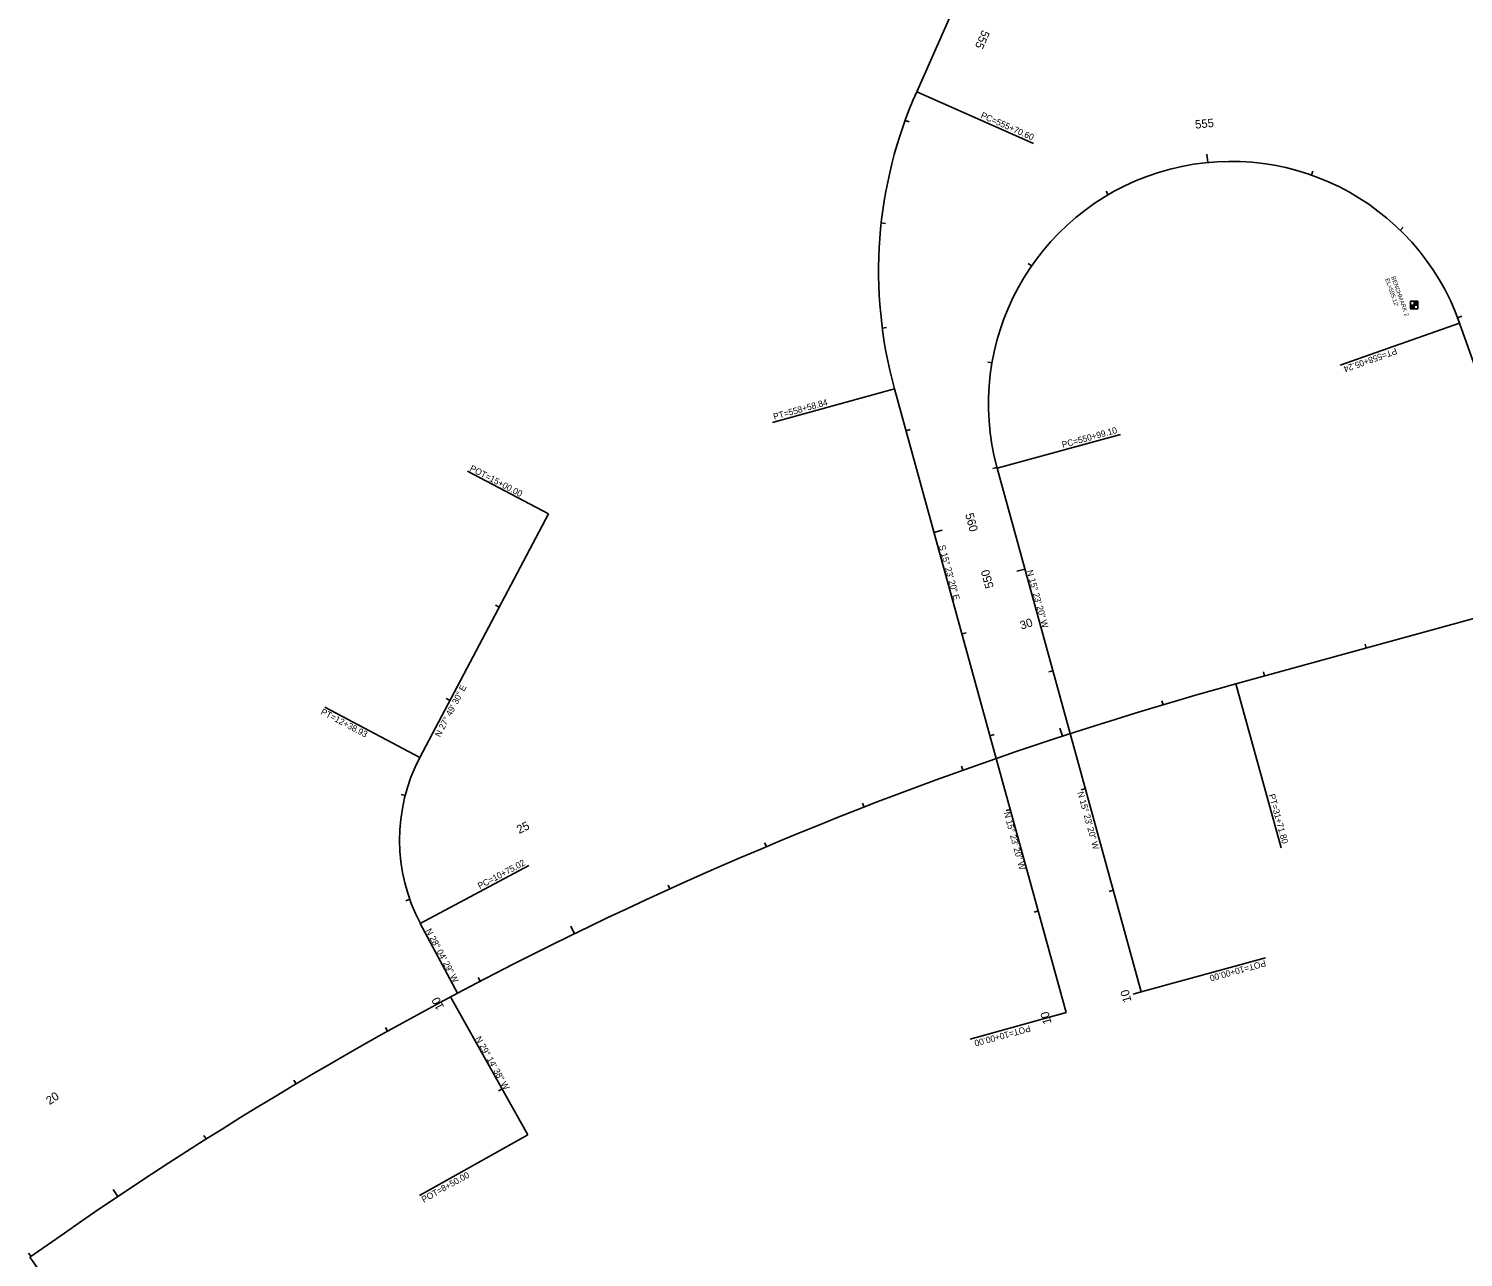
# Model space of a CAD drawing. Extents: x 2004390 to 2008791, y 1133870 to 1140084.
# Drawn here: x 2004390 to 2005751, y 1136432 to 1137597 of the extents above; entities that cross this region are included whole.
import ezdxf

# ---------------------------------------------------------------- set-up
doc = ezdxf.new("R2010")
doc.units = 0
for name, color, linetype in [('RD_HC_Cl', 7, 'Continuous'), ('RD_HC_CL_Rel', 7, 'Continuous'), ('RD_HC_Data', 7, 'Continuous'), ('RD_HC_Data_Rel', 7, 'Continuous'), ('RD_HC_Data_Tic', 7, 'Continuous'), ('RD_HC_Data_Tic_Rel', 7, 'Continuous'), ('RD_HC_Survey', 7, 'Continuous'), ('RD_HC_Survey_txCode', 7, 'Continuous'), ('RD_HC_TX_Rel_Sta50', 7, 'Continuous'), ('RD_HC_TX_Sta50', 7, 'Continuous')]:
    doc.layers.add(name, color=color, linetype=linetype)

msp = doc.modelspace()

# ---------------------------------------------------------------- linework, layer by layer
at = {"layer": 'RD_HC_Cl'}
for p, q in [((2005379.4, 1137869.6), (2005232, 1137537.6)), ((2005747, 1137318.2), (2006250.3, 1135895.5)), ((2005211, 1137255.8), (2005307.4, 1136905.2)), ((2005377.7, 1136928.8), (2005308.4, 1137180.5)), ((2004760.8, 1136906.3), (2004882.7, 1137137.2)), ((2005445.1, 1136683.8), (2005377.7, 1136928.8)), ((2005373.8, 1136664.2), (2005307.4, 1136905.2)), ((2004796.5, 1136682.6), (2004761.1, 1136748.8)), ((2004863.1, 1136548.2), (2004789.8, 1136679.1))]:
    msp.add_line(p, q, dxfattribs=at)
for centre, radius, start, end in [((2005615.9, 1137367.2), 420, 156.0681, 195.3889), ((2005530.2, 1137241.5), 230, 19.482, 195.3889), ((2004909.4, 1136827.9), 168, 152.175, 208.0747)]:
    msp.add_arc(centre, radius, start, end, dxfattribs=at)
at = {"layer": 'RD_HC_CL_Rel'}
msp.add_line((2005534.9, 1136975.9), (2006420.4, 1137219.7), dxfattribs=at)
msp.add_arc((2006499.8, 1133470.3), 3636, 105.3889, 125.452, dxfattribs=at)
at = {"layer": 'RD_HC_Data'}
for p, q in [((2005232, 1137537.6), (2005342.7, 1137488.5)), ((2005747, 1137318.2), (2005633.8, 1137278.2)), ((2005095.2, 1137223.9), (2005211, 1137255.8)), ((2005308.4, 1137180.5), (2005425.2, 1137212.6)), ((2004882.7, 1137137.2), (2004805.8, 1137177.8)), ((2004670.5, 1136954), (2004760.8, 1136906.3)), ((2004761.1, 1136748.8), (2004864, 1136803.7)), ((2005562.8, 1136716.2), (2005445.1, 1136683.8)), ((2005373.8, 1136664.2), (2005282.8, 1136639.1)), ((2004863.1, 1136548.2), (2004760.5, 1136490.8))]:
    msp.add_line(p, q, dxfattribs=at)
at = {"layer": 'RD_HC_Data_Rel'}
for p, q in [((2005534.9, 1136975.9), (2005577.7, 1136820.4)), ((2004390.8, 1136432.2), (2004485.4, 1136299.3))]:
    msp.add_line(p, q, dxfattribs=at)
at = {"layer": 'RD_HC_Data_Tic'}
for p, q in [((2005221, 1137510.3), (2005224.8, 1137509)), ((2005508.1, 1137470.5), (2005507.3, 1137478.4)), ((2005606.6, 1137458.5), (2005607.9, 1137462.2)), ((2005413.7, 1137439.8), (2005411.7, 1137443.3)), ((2005198.4, 1137413.2), (2005202.4, 1137412.7)), ((2005690.8, 1137406.1), (2005693.6, 1137409)), ((2005341, 1137372.3), (2005337.7, 1137374.6)), ((2005199.4, 1137313.4), (2005203.3, 1137313.9)), ((2005745.2, 1137323.1), (2005749, 1137324.6)), ((2005303.5, 1137280.4), (2005299.6, 1137281.1)), ((2005221.9, 1137216.1), (2005225.7, 1137217.1)), ((2005308.2, 1137181.3), (2005304.3, 1137180.3)), ((2005248.4, 1137119.7), (2005256.1, 1137121.8)), ((2005334.7, 1137084.9), (2005327, 1137082.8)), ((2004836, 1137048.8), (2004832.5, 1137050.6)), ((2005275, 1137023.3), (2005278.8, 1137024.3)), ((2005361.3, 1136988.5), (2005357.4, 1136987.5)), ((2004789.3, 1136960.3), (2004785.8, 1136962.2)), ((2005301.5, 1136926.8), (2005305.4, 1136927.9)), ((2005392.1, 1136876.7), (2005388.2, 1136875.6)), ((2004746.8, 1136870.1), (2004742.9, 1136871.1)), ((2005320.7, 1136857), (2005316.9, 1136856)), ((2004751.1, 1136771.7), (2004747.3, 1136770.3)), ((2005418.6, 1136780.2), (2005414.7, 1136779.2)), ((2005347.3, 1136760.6), (2005343.4, 1136759.5)), ((2004796.5, 1136682.6), (2004789.4, 1136678.9)), ((2005445.1, 1136683.8), (2005437.4, 1136681.7)), ((2005373.8, 1136664.2), (2005366.1, 1136662.1)), ((2004838.7, 1136591.9), (2004835.2, 1136589.9))]:
    msp.add_line(p, q, dxfattribs=at)
at = {"layer": 'RD_HC_Data_Tic_Rel'}
for p, q in [((2005658.5, 1137009.9), (2005657.4, 1137013.8)), ((2005562.1, 1136983.4), (2005561, 1136987.3)), ((2005465.8, 1136956.2), (2005464.7, 1136960)), ((2005370.4, 1136926.4), (2005367.9, 1136934)), ((2005275.8, 1136894.1), (2005274.4, 1136897.8)), ((2005182.1, 1136859.1), (2005180.6, 1136862.8)), ((2005089.4, 1136821.6), (2005087.8, 1136825.3)), ((2004997.8, 1136781.5), (2004996.1, 1136785.2)), ((2004907.3, 1136739), (2004903.8, 1136746.2)), ((2004818, 1136694), (2004816.1, 1136697.5)), ((2004730, 1136646.5), (2004728, 1136650)), ((2004643.3, 1136596.6), (2004641.2, 1136600.1)), ((2004558, 1136544.4), (2004555.9, 1136547.8)), ((2004474.2, 1136489.8), (2004469.8, 1136496.5)), ((2004391.9, 1136433), (2004389.6, 1136436.2))]:
    msp.add_line(p, q, dxfattribs=at)
at = {"layer": 'RD_HC_Survey'}
for p, q in [((2005704, 1137338.8), (2005704, 1137331.7)), ((2005704, 1137338.8), (2005704, 1137335.2)), ((2005704.1, 1137338.8), (2005704.1, 1137335.2)), ((2005704.1, 1137338.8), (2005704.1, 1137335.2)), ((2005704.2, 1137338.8), (2005704.2, 1137335.2)), ((2005704.2, 1137338.8), (2005704.2, 1137335.2)), ((2005704.3, 1137338.8), (2005704.3, 1137335.2)), ((2005704.3, 1137338.8), (2005704.3, 1137335.2)), ((2005704.4, 1137338.8), (2005704.4, 1137335.2)), ((2005704.4, 1137338.8), (2005704.4, 1137335.2)), ((2005704.5, 1137338.8), (2005704.5, 1137335.2)), ((2005704.5, 1137338.8), (2005704.5, 1137335.2)), ((2005704.6, 1137338.8), (2005704.6, 1137335.2)), ((2005704.6, 1137338.8), (2005704.6, 1137335.2)), ((2005704.7, 1137338.8), (2005704.7, 1137335.2)), ((2005704.7, 1137338.8), (2005704.7, 1137335.2)), ((2005704.8, 1137338.8), (2005704.8, 1137335.2)), ((2005704.8, 1137338.8), (2005704.8, 1137335.2)), ((2005704.9, 1137338.8), (2005704.9, 1137335.2)), ((2005704.9, 1137338.8), (2005704.9, 1137335.2)), ((2005705, 1137338.8), (2005705, 1137335.2)), ((2005705, 1137338.8), (2005705, 1137335.2)), ((2005705.1, 1137338.8), (2005705.1, 1137335.2)), ((2005705.1, 1137338.8), (2005705.1, 1137335.2)), ((2005705.2, 1137338.8), (2005705.2, 1137335.2)), ((2005705.2, 1137338.8), (2005705.2, 1137335.2)), ((2005705.3, 1137338.8), (2005705.3, 1137335.2)), ((2005705.3, 1137338.8), (2005705.3, 1137335.2)), ((2005705.4, 1137338.8), (2005705.4, 1137335.2)), ((2005705.4, 1137338.8), (2005705.4, 1137335.2)), ((2005705.5, 1137338.8), (2005705.5, 1137335.2)), ((2005705.5, 1137338.8), (2005705.5, 1137335.2)), ((2005705.6, 1137338.8), (2005705.6, 1137335.2)), ((2005705.6, 1137338.8), (2005705.6, 1137335.2)), ((2005705.7, 1137338.8), (2005705.7, 1137335.2)), ((2005705.7, 1137338.8), (2005705.7, 1137335.2)), ((2005705.8, 1137338.8), (2005705.8, 1137335.2)), ((2005705.8, 1137338.8), (2005705.8, 1137335.2)), ((2005705.9, 1137338.8), (2005705.9, 1137335.2)), ((2005705.9, 1137338.8), (2005705.9, 1137335.2)), ((2005706, 1137338.8), (2005706, 1137335.2)), ((2005706, 1137338.8), (2005706, 1137335.2)), ((2005706.1, 1137338.8), (2005706.1, 1137335.2)), ((2005706.1, 1137338.8), (2005706.1, 1137335.2)), ((2005706.2, 1137338.8), (2005706.2, 1137335.2)), ((2005706.2, 1137338.8), (2005706.2, 1137335.2)), ((2005706.3, 1137338.8), (2005706.3, 1137335.2)), ((2005706.3, 1137338.8), (2005706.3, 1137335.2)), ((2005706.4, 1137338.8), (2005706.4, 1137335.2)), ((2005706.4, 1137338.8), (2005706.4, 1137335.2)), ((2005706.5, 1137338.8), (2005706.5, 1137335.2)), ((2005706.5, 1137338.8), (2005706.5, 1137335.2)), ((2005706.6, 1137338.8), (2005706.6, 1137335.2)), ((2005706.6, 1137338.8), (2005706.6, 1137335.2)), ((2005706.7, 1137338.8), (2005706.7, 1137335.2)), ((2005706.7, 1137338.8), (2005706.7, 1137335.2)), ((2005706.8, 1137338.8), (2005706.8, 1137335.2)), ((2005706.8, 1137338.8), (2005706.8, 1137335.2)), ((2005706.9, 1137338.8), (2005706.9, 1137335.2)), ((2005706.9, 1137338.8), (2005706.9, 1137335.2)), ((2005707, 1137338.8), (2005707, 1137335.2)), ((2005707, 1137338.8), (2005707, 1137335.2)), ((2005707.1, 1137338.8), (2005707.1, 1137335.2)), ((2005707.1, 1137338.8), (2005707.1, 1137335.2)), ((2005707.2, 1137338.8), (2005707.2, 1137335.2)), ((2005707.2, 1137338.8), (2005707.2, 1137335.2)), ((2005707.3, 1137338.8), (2005707.3, 1137335.2)), ((2005707.3, 1137338.8), (2005707.3, 1137335.2)), ((2005707.4, 1137338.8), (2005707.4, 1137335.2)), ((2005707.4, 1137338.8), (2005707.4, 1137335.2)), ((2005707.5, 1137338.8), (2005707.5, 1137335.2)), ((2005707.5, 1137335.2), (2005700.4, 1137335.2)), ((2005700.4, 1137335.2), (2005700.4, 1137331.7)), ((2005700.5, 1137335.2), (2005700.5, 1137331.7)), ((2005700.5, 1137335.2), (2005700.5, 1137331.7)), ((2005700.6, 1137335.2), (2005700.6, 1137331.7)), ((2005700.6, 1137335.2), (2005700.6, 1137331.7)), ((2005700.7, 1137335.2), (2005700.7, 1137331.7)), ((2005700.7, 1137335.2), (2005700.7, 1137331.7)), ((2005700.8, 1137335.2), (2005700.8, 1137331.7)), ((2005700.8, 1137335.2), (2005700.8, 1137331.7)), ((2005700.9, 1137335.2), (2005700.9, 1137331.7)), ((2005700.9, 1137335.2), (2005700.9, 1137331.7)), ((2005701, 1137335.2), (2005701, 1137331.7)), ((2005701, 1137335.2), (2005701, 1137331.7)), ((2005701.1, 1137335.2), (2005701.1, 1137331.7)), ((2005701.1, 1137335.2), (2005701.1, 1137331.7)), ((2005701.2, 1137335.2), (2005701.2, 1137331.7)), ((2005701.2, 1137335.2), (2005701.2, 1137331.7)), ((2005701.3, 1137335.2), (2005701.3, 1137331.7)), ((2005701.3, 1137335.2), (2005701.3, 1137331.7)), ((2005701.4, 1137335.2), (2005701.4, 1137331.7)), ((2005701.4, 1137335.2), (2005701.4, 1137331.7)), ((2005701.5, 1137335.2), (2005701.5, 1137331.7)), ((2005701.5, 1137335.2), (2005701.5, 1137331.7)), ((2005701.6, 1137335.2), (2005701.6, 1137331.7)), ((2005701.6, 1137335.2), (2005701.6, 1137331.7)), ((2005701.7, 1137335.2), (2005701.7, 1137331.7)), ((2005701.7, 1137335.2), (2005701.7, 1137331.7)), ((2005701.8, 1137335.2), (2005701.8, 1137331.7)), ((2005701.8, 1137335.2), (2005701.8, 1137331.7)), ((2005701.9, 1137335.2), (2005701.9, 1137331.7)), ((2005701.9, 1137335.2), (2005701.9, 1137331.7)), ((2005702, 1137335.2), (2005702, 1137331.7)), ((2005702, 1137335.2), (2005702, 1137331.7)), ((2005702.1, 1137335.2), (2005702.1, 1137331.7)), ((2005702.1, 1137335.2), (2005702.1, 1137331.7)), ((2005702.2, 1137335.2), (2005702.2, 1137331.7)), ((2005702.2, 1137335.2), (2005702.2, 1137331.7)), ((2005702.3, 1137335.2), (2005702.3, 1137331.7)), ((2005702.3, 1137335.2), (2005702.3, 1137331.7)), ((2005702.4, 1137335.2), (2005702.4, 1137331.7)), ((2005702.4, 1137335.2), (2005702.4, 1137331.7)), ((2005702.5, 1137335.2), (2005702.5, 1137331.7)), ((2005702.5, 1137335.2), (2005702.5, 1137331.7)), ((2005702.6, 1137335.2), (2005702.6, 1137331.7)), ((2005702.6, 1137335.2), (2005702.6, 1137331.7)), ((2005702.7, 1137335.2), (2005702.7, 1137331.7)), ((2005702.7, 1137335.2), (2005702.7, 1137331.7)), ((2005702.8, 1137335.2), (2005702.8, 1137331.7)), ((2005702.8, 1137335.2), (2005702.8, 1137331.7)), ((2005702.9, 1137335.2), (2005702.9, 1137331.7)), ((2005702.9, 1137335.2), (2005702.9, 1137331.7)), ((2005703, 1137335.2), (2005703, 1137331.7)), ((2005703, 1137335.2), (2005703, 1137331.7)), ((2005703.1, 1137335.2), (2005703.1, 1137331.7)), ((2005703.1, 1137335.2), (2005703.1, 1137331.7)), ((2005703.2, 1137335.2), (2005703.2, 1137331.7)), ((2005703.2, 1137335.2), (2005703.2, 1137331.7)), ((2005703.3, 1137335.2), (2005703.3, 1137331.7)), ((2005703.3, 1137335.2), (2005703.3, 1137331.7)), ((2005703.4, 1137335.2), (2005703.4, 1137331.7)), ((2005703.4, 1137335.2), (2005703.4, 1137331.7)), ((2005703.5, 1137335.2), (2005703.5, 1137331.7)), ((2005703.5, 1137335.2), (2005703.5, 1137331.7)), ((2005703.6, 1137335.2), (2005703.6, 1137331.7)), ((2005703.6, 1137335.2), (2005703.6, 1137331.7)), ((2005703.7, 1137335.2), (2005703.7, 1137331.7)), ((2005703.7, 1137335.2), (2005703.7, 1137331.7)), ((2005703.8, 1137335.2), (2005703.8, 1137331.7)), ((2005703.8, 1137335.2), (2005703.8, 1137331.7)), ((2005703.9, 1137335.2), (2005703.9, 1137331.7)), ((2005703.9, 1137335.2), (2005703.9, 1137331.7))]:
    msp.add_line(p, q, dxfattribs=at)
msp.add_lwpolyline([(2005707.5, 1137338.8), (2005700.4, 1137338.8), (2005700.4, 1137331.7), (2005707.5, 1137331.7)], close=True, dxfattribs=at)

# ---------------------------------------------------------------- texts
at = {"layer": 'RD_HC_Data'}
for s, rotation, p in [('PC=555+70.60', 336.0681, (2005292.2, 1137513.1)), ('PT=558+05.24', 199.482, (2005686.4, 1137294.7)), ('PT=558+58.84', 15.3889, (2005096.9, 1137226.4)), ('PC=550+99.10', 15.3889, (2005370.6, 1137199.7)), ('POT=15+00.00', 332.175, (2004807.5, 1137178.6)), ('S 15%%d 23\' 20" E', 285.3889, (2005253, 1137106.9)), ('N 15%%d 23\' 20" W', 285.3889, (2005336.3, 1137083.1)), ('N 27%%d 49\' 30" E', 62.175, (2004779.8, 1136925)), ('PT=12+38.93', 332.175, (2004666.1, 1136947.6)), ('N 15%%d 23\' 20" W', 285.3889, (2005384.5, 1136873)), ('N 15%%d 23\' 20" W', 285.3889, (2005314.5, 1136853.8)), ('PC=10+75.02', 28.0747, (2004817.6, 1136781.2)), ('N 28%%d 04\' 29" W', 298.0747, (2004765.9, 1136742)), ('POT=10+00.00', 195.3889, (2005562.3, 1136714.1)), ('POT=10+00.00', 195.3889, (2005339.1, 1136652.3)), ('N 29%%d 14\' 38" W', 299.2438, (2004813.1, 1136639.7)), ('POT=8+50.00', 29.2438, (2004764.4, 1136483.8))]:
    msp.add_text(s, height=6, rotation=rotation, dxfattribs=at).set_placement(p)
at = {"layer": 'RD_HC_Data_Rel'}
msp.add_text('PT=31+71.80', height=6, rotation=285.3889, dxfattribs=at).set_placement((2005565.9, 1136870.7))
at = {"layer": 'RD_HC_Survey_txCode'}
for s, p in [("EL=595.12'", (2005676.4, 1137359.8)), ('BENCHMARK 2', (2005682.1, 1137361.8))]:
    msp.add_text(s, height=4, rotation=289.4494, dxfattribs=at).set_placement(p)
at = {"layer": 'RD_HC_TX_Rel_Sta50'}
for s, rotation, p in [('30', 18.0961, (2005331.5, 1137027.3)), ('25', 25.9751, (2004854.9, 1136833.6)), ('20', 33.854, (2004409.4, 1136576.4))]:
    msp.add_text(s, height=8, rotation=rotation, dxfattribs=at).set_placement(p)
at = {"layer": 'RD_HC_TX_Sta50'}
for s, rotation, p in [('555', 246.0681, (2005294.3, 1137596.7)), ('555', 5.5209, (2005496.5, 1137502.5)), ('560', 285.3889, (2005277.9, 1137136.8)), ('550', 105.3889, (2005305.2, 1137067.8)), ('10', 105.3889, (2005435.9, 1136675.2)), ('10', 118.0747, (2004784, 1136669.4)), ('10', 105.3889, (2005360, 1136654.4))]:
    msp.add_text(s, height=8, rotation=rotation, dxfattribs=at).set_placement(p)

doc.saveas('drawing.dxf')
